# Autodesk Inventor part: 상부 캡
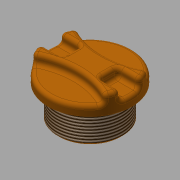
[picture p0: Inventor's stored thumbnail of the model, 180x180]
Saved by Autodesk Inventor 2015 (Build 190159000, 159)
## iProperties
Created: 2016-09
Part Number: 상부 캡
Material: ABS 플라스틱
Document SubType Name: Modeling
Designer: mduedu
Density: 1.06 g/cm^3
Mass: 23.0415 g
Surface Area: 69.3209 cm^2
Volume: 21.7373 cm^3
Appearance: 주황색
Author: mduedu
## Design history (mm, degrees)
sketch "스케치1"
  geometry: C1 r 22.5 at (0, 0); 1 further point
  constraints: 1 centre point, 1 coincident
  dimensions: "d0" = 45 diameter of C1
extrude "돌출1" new body sketch "스케치1" distance "d1" = 10; taper "d2" = 0 deg
sketch "스케치2" dims "d4" = 80
  geometry: C1 r 22.5 at (0, 0) reference; 3 further points
  constraints: 3 vertical alignment, 2 other
  dimensions: "d3" = 7 distance of point (0, 7) point (0, 0)
extrude "돌출2" cut sketch "스케치2" distance "d5" = 5; taper "d6" = 0 deg
sketch "스케치3"
  geometry: L1 (-22.5, 0)-(0, 0); L2 (-21.937, 5)-(-10, 5); L3 (-10, 5)-(-10, -5); L4 (-10, -5)-(-21.937, -5); A1 r 22.5 centre (0, 0) between (-19.118, 11.864) and (-19.118, -11.864) reference; A2 r 22.5 centre (0, 0) between (-21.937, 5) and (-21.937, -5); 1 further point
  constraints: 8 end point, 5 point on circle, 2 horizontal, 1 centre point, 1 coincident, 1 parallel, 1 perpendicular, 1 symmetric about line
  dimensions: "d7" = 10 distance from line of L3 point (0, 0); "d8" = 10 distance of L2.end L3.end
extrude "돌출3" cut sketch "스케치3" distance "d9" = 5; taper "d10" = 0 deg
fillet "모깎기1" dims "d11" = 2
fillet "모깎기2" dims "d12" = 2
fillet "모깎기3" dims "d13" = 2
sketch "스케치4"
  geometry: C1 r 17.5 at (0, 0); 1 further point
  constraints: 1 centre point, 1 coincident
  dimensions: "d14" = 35 diameter of C1
extrude "돌출4" join sketch "스케치4" distance "d15" = 17; taper "d16" = 0 deg
sketch "스케치5"
  geometry: C1 r 12.5 at (0, 0); 1 further point
  constraints: 1 centre point, 1 coincident
  dimensions: "d17" = 25 diameter of C1
extrude "돌출5" cut sketch "스케치5" distance "d18" = 10; taper "d19" = 0 deg
fillet "모깎기4" dims "d20" = 3
sketch "스케치6"
  geometry: L1 (0, 22.5)-(0, -22.5) reference; L2 (0, 17.5)-(-1, 17.5); L3 (-1, 17.5)-(-1, 16.5); L4 (-1, 16.5)-(0, 16.5); L5 (0, 16.5)-(0, 17.5); L6 (0, 17.5)-(-17, 17.5) reference; L7 (-22.401, 0)-(15.404, 0) reference; 1 further point
  constraints: 8 end point, 2 parallel, 1 collinear, 1 horizontal, 1 perpendicular, 1 point on line
  dimensions: "d26" = 1 distance of L2.start L2.end; "d28" = 1 distance of L2.end L3.end
revolve "회전1" sketch "스케치6" stored, may be unused: angle "d29" = 90 deg
feature "스레드1" dims "d21" = 10, "d22" = 0
chamfer "모따기1" distance "d23" = 1; stored, may be unused: second distance "d24" = 2, angle "d25" = 45 deg
chamfer "모따기2" distance "d30" = 1; stored, may be unused: second distance "d31" = 2, angle "d32" = 45 deg
node "솔리드1"
mirror "대칭1"
mirror "대칭2"
node "투영된 루프1"
